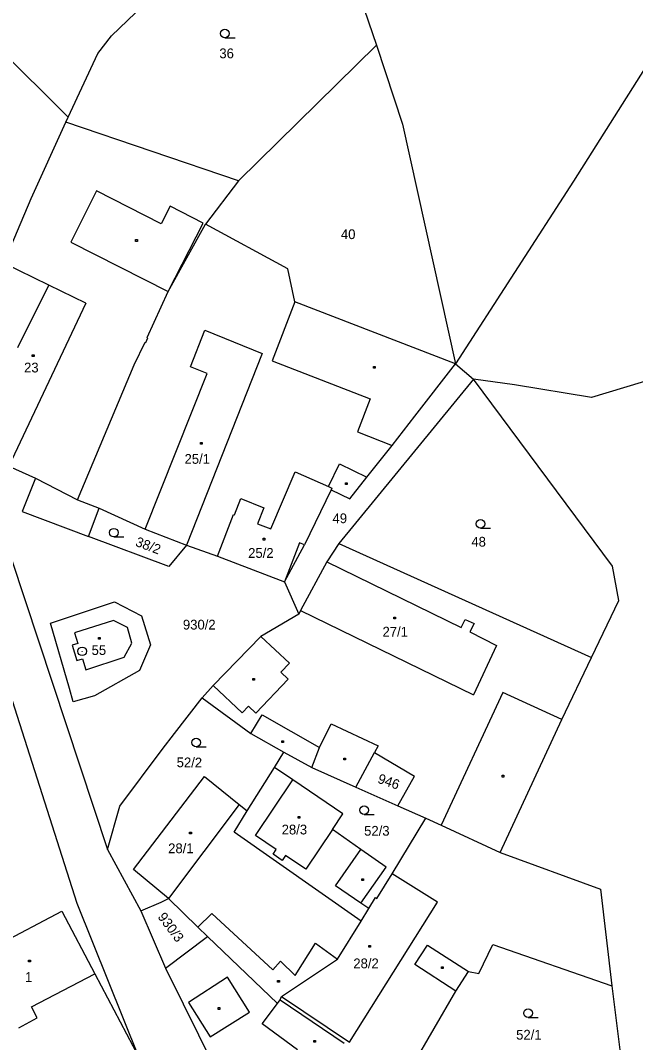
# Model space of a CAD drawing. Extents: x -796130 to -793145, y -1109506 to -1106267.
# Drawn here: x -794498.3 to -794391.3, y -1107830.1 to -1107652.3 of the extents above; entities that cross this region are included whole.
import ezdxf

# ---------------------------------------------------------------- set-up
doc = ezdxf.new("R2010")
doc.units = 0
for name, color, linetype in [('Vrstva 1', 7, 'Continuous'), ('Vrstva 14', 7, 'Continuous'), ('Vrstva 15', 7, 'Continuous'), ('Vrstva 2', 7, 'Continuous'), ('Vrstva 23', 7, 'Continuous'), ('Vrstva 25', 7, 'Continuous'), ('Vrstva 28', 7, 'Continuous')]:
    doc.layers.add(name, color=color, linetype=linetype)

msp = doc.modelspace()

# ---------------------------------------------------------------- linework, layer by layer
at = {"layer": 'Vrstva 1'}
for p, q in [((-794482.48, -1107655.02), (-794453.53, -1107627.17)), ((-794441.8, -1107640.76), (-794436.37, -1107656.6)), ((-794382.04, -1107648.53), (-794402.09, -1107680.28)), ((-794505.95, -1107653.34), (-794489.99, -1107669.12)), ((-794484.84, -1107658.08), (-794482.48, -1107655.02)), ((-794436.37, -1107656.6), (-794460.35, -1107680.23)), ((-794436.37, -1107656.6), (-794431.83, -1107670.33)), ((-794489.99, -1107669.12), (-794484.84, -1107658.08)), ((-794490.38, -1107669.98), (-794489.99, -1107669.12)), ((-794496.41, -1107683.31), (-794490.38, -1107669.98)), ((-794460.35, -1107680.23), (-794490.38, -1107669.98)), ((-794431.83, -1107670.33), (-794422.61, -1107712.07)), ((-794460.35, -1107680.23), (-794466.1, -1107687.77)), ((-794402.09, -1107680.28), (-794422.61, -1107712.07)), ((-794501.21, -1107694.54), (-794496.41, -1107683.31)), ((-794472.62, -1107699.47), (-794466.1, -1107687.77)), ((-794451.75, -1107695.51), (-794466.1, -1107687.77)), ((-794493.34, -1107698.36), (-794501.21, -1107694.54)), ((-794450.55, -1107701.26), (-794451.75, -1107695.51)), ((-794498.75, -1107709.22), (-794493.34, -1107698.36)), ((-794476.26, -1107707.48), (-794472.62, -1107699.47)), ((-794422.61, -1107712.07), (-794450.55, -1107701.26)), ((-794478.52, -1107712.24), (-794476.62, -1107708.28)), ((-794476.62, -1107708.28), (-794476.48, -1107708.35)), ((-794476.48, -1107708.35), (-794476.12, -1107707.54)), ((-794476.12, -1107707.54), (-794476.26, -1107707.48)), ((-794488.39, -1107735.72), (-794478.52, -1107712.24)), ((-794429.7, -1107721.12), (-794422.61, -1107712.07)), ((-794422.61, -1107712.07), (-794419.45, -1107714.72)), ((-794382.35, -1107712.86), (-794398.91, -1107717.92)), ((-794419.45, -1107714.72), (-794442.9, -1107743.28)), ((-794395.26, -1107747.22), (-794419.45, -1107714.72)), ((-794412.32, -1107715.7), (-794419.45, -1107714.72)), ((-794398.91, -1107717.92), (-794412.32, -1107715.7)), ((-794433.65, -1107726.24), (-794429.7, -1107721.12)), ((-794438.02, -1107731.74), (-794433.65, -1107726.24)), ((-794506.09, -1107727.3), (-794483.18, -1107796.53)), ((-794500.34, -1107729.85), (-794495.7, -1107731.95)), ((-794495.7, -1107731.95), (-794498.02, -1107737.75)), ((-794454.75, -1107740.77), (-794450.53, -1107730.83)), ((-794450.53, -1107730.83), (-794444.72, -1107733.38)), ((-794441, -1107735.5), (-794438.02, -1107731.74)), ((-794444.72, -1107733.38), (-794444.11, -1107733.65)), ((-794444.11, -1107733.65), (-794444.26, -1107733.95)), ((-794461.04, -1107738.32), (-794459.97, -1107735.49)), ((-794459.97, -1107735.49), (-794455.96, -1107737.08)), ((-794444.26, -1107733.95), (-794448.85, -1107743.51)), ((-794444.26, -1107733.95), (-794441, -1107735.5)), ((-794488.39, -1107735.72), (-794484.6, -1107737.13)), ((-794486.45, -1107742.05), (-794484.6, -1107737.13)), ((-794484.6, -1107737.13), (-794476.6, -1107740.79)), ((-794455.96, -1107737.08), (-794457.03, -1107739.9)), ((-794498.02, -1107737.75), (-794486.45, -1107742.05)), ((-794464.03, -1107745.51), (-794461.21, -1107738.26)), ((-794461.21, -1107738.26), (-794461.04, -1107738.32)), ((-794476.6, -1107740.79), (-794469.41, -1107743.61)), ((-794457.03, -1107739.9), (-794454.75, -1107740.77)), ((-794472.51, -1107747.3), (-794486.45, -1107742.05)), ((-794469.41, -1107743.61), (-794472.51, -1107747.3)), ((-794469.41, -1107743.61), (-794464.03, -1107745.51)), ((-794452.37, -1107749.98), (-794448.85, -1107743.51)), ((-794442.9, -1107743.28), (-794445, -1107746.46)), ((-794442.9, -1107743.28), (-794398.95, -1107763.14)), ((-794464.03, -1107745.51), (-794452.37, -1107749.98)), ((-794445, -1107746.46), (-794449.56, -1107754.93)), ((-794394.2, -1107753.2), (-794395.26, -1107747.22)), ((-794452.37, -1107749.98), (-794449.87, -1107755.61)), ((-794488.44, -1107805.91), (-794505.52, -1107752.46)), ((-794398.95, -1107763.14), (-794394.2, -1107753.2)), ((-794493.07, -1107757.13), (-794481.91, -1107753.47)), ((-794481.91, -1107753.47), (-794477.23, -1107755.89)), ((-794449.56, -1107754.93), (-794449.87, -1107755.61)), ((-794477.23, -1107755.89), (-794475.7, -1107760.9)), ((-794449.87, -1107755.61), (-794456.45, -1107759.45)), ((-794489.79, -1107768.5), (-794493.07, -1107757.13)), ((-794456.45, -1107759.45), (-794464.79, -1107768.01)), ((-794475.7, -1107760.9), (-794477.6, -1107765.39)), ((-794404.1, -1107773.92), (-794398.95, -1107763.14)), ((-794477.6, -1107765.39), (-794485.43, -1107769.78)), ((-794489.11, -1107770.86), (-794489.79, -1107768.5)), ((-794464.79, -1107768.01), (-794466.67, -1107770.15)), ((-794485.43, -1107769.78), (-794489.11, -1107770.86)), ((-794471.5, -1107776.37), (-794466.67, -1107770.15)), ((-794466.67, -1107770.15), (-794458.22, -1107776.36)), ((-794414.84, -1107797.02), (-794404.1, -1107773.92)), ((-794473.65, -1107779.15), (-794471.5, -1107776.37)), ((-794458.22, -1107776.36), (-794452.45, -1107779.58)), ((-794481.02, -1107788.97), (-794473.65, -1107779.15)), ((-794454.1, -1107782.23), (-794452.45, -1107779.58)), ((-794452.45, -1107779.58), (-794447.59, -1107782.27)), ((-794439.97, -1107785.68), (-794436.72, -1107779.66)), ((-794436.72, -1107779.66), (-794429.75, -1107783.76)), ((-794458.83, -1107789.82), (-794454.1, -1107782.23)), ((-794450.92, -1107784.39), (-794454.1, -1107782.23)), ((-794447.59, -1107782.27), (-794439.97, -1107785.68)), ((-794478.64, -1107800), (-794466.3, -1107783.82)), ((-794466.3, -1107783.82), (-794460.24, -1107788.69)), ((-794442.19, -1107790.32), (-794450.92, -1107784.39)), ((-794432.61, -1107788.93), (-794429.75, -1107783.76)), ((-794439.97, -1107785.68), (-794432.61, -1107788.93)), ((-794483.18, -1107796.53), (-794481.02, -1107788.97)), ((-794460.24, -1107788.69), (-794458.83, -1107789.82)), ((-794432.61, -1107788.93), (-794427.74, -1107791.09)), ((-794461.11, -1107793.49), (-794458.83, -1107789.82)), ((-794444.01, -1107793.03), (-794442.19, -1107790.32)), ((-794433.65, -1107800.74), (-794427.74, -1107791.09)), ((-794427.74, -1107791.09), (-794425.07, -1107792.27)), ((-794425.07, -1107792.27), (-794414.84, -1107797.02)), ((-794439.04, -1107809.01), (-794461.11, -1107793.49)), ((-794439.07, -1107796.51), (-794444.01, -1107793.03)), ((-794483.18, -1107796.53), (-794477.35, -1107807.18)), ((-794434.69, -1107799.61), (-794439.07, -1107796.51)), ((-794414.84, -1107797.02), (-794397.36, -1107803.4)), ((-794439.09, -1107805.87), (-794434.69, -1107799.61)), ((-794472.53, -1107805.03), (-794478.64, -1107800)), ((-794436.29, -1107805.04), (-794433.65, -1107800.74)), ((-794437.68, -1107806.79), (-794436.5, -1107804.89)), ((-794436.5, -1107804.89), (-794436.29, -1107805.04)), ((-794397.36, -1107803.4), (-794395.39, -1107820.21)), ((-794477.65, -1107832.78), (-794488.44, -1107805.91)), ((-794477.35, -1107807.18), (-794473.81, -1107805.66)), ((-794473.81, -1107805.66), (-794472.53, -1107805.03)), ((-794467.46, -1107810.01), (-794472.53, -1107805.03)), ((-794437.68, -1107806.79), (-794439.09, -1107805.87)), ((-794521.11, -1107823.01), (-794491.09, -1107807.24)), ((-794491.09, -1107807.24), (-794485.37, -1107818.12)), ((-794477.35, -1107807.18), (-794473.05, -1107817.18)), ((-794439.04, -1107809.01), (-794437.68, -1107806.79)), ((-794465.73, -1107811.67), (-794467.46, -1107810.01)), ((-794443.11, -1107815.6), (-794439.04, -1107809.01)), ((-794473.05, -1107817.18), (-794465.73, -1107811.67)), ((-794465.73, -1107811.67), (-794453.58, -1107823.33)), ((-794418.56, -1107818.08), (-794416.08, -1107813.05)), ((-794416.08, -1107813.05), (-794395.39, -1107820.21)), ((-794452.88, -1107822.06), (-794443.11, -1107815.6)), ((-794473.05, -1107817.18), (-794470, -1107823.36)), ((-794485.37, -1107818.12), (-794477.65, -1107832.78)), ((-794422.52, -1107821.15), (-794420.33, -1107817.76)), ((-794420.33, -1107817.76), (-794418.56, -1107818.08)), ((-794395.39, -1107820.21), (-794393.06, -1107838.97)), ((-794453.58, -1107823.33), (-794453.1, -1107822.64)), ((-794453.1, -1107822.64), (-794452.88, -1107822.06)), ((-794453.1, -1107822.64), (-794441.95, -1107830.18)), ((-794430.51, -1107834.81), (-794422.52, -1107821.15)), ((-794470, -1107823.36), (-794462.61, -1107838.31))]:
    msp.add_line(p, q, dxfattribs=at)
at = {"layer": 'Vrstva 2'}
for p, q in [((-794485.07, -1107681.94), (-794489.51, -1107690.89)), ((-794473.82, -1107687.69), (-794485.07, -1107681.94)), ((-794472.25, -1107684.61), (-794473.82, -1107687.69)), ((-794466.5, -1107687.56), (-794472.25, -1107684.61)), ((-794472.62, -1107699.47), (-794466.5, -1107687.56)), ((-794489.51, -1107690.89), (-794472.62, -1107699.47)), ((-794486.91, -1107701.49), (-794493.34, -1107698.36)), ((-794486.91, -1107701.49), (-794500.34, -1107729.85)), ((-794450.55, -1107701.26), (-794454.51, -1107711.5)), ((-794468.7, -1107712.55), (-794466.21, -1107706.16)), ((-794466.21, -1107706.16), (-794456.24, -1107710.25)), ((-794456.24, -1107710.25), (-794469.41, -1107743.61)), ((-794465.8, -1107713.72), (-794468.7, -1107712.55)), ((-794454.51, -1107711.5), (-794437.46, -1107718.14)), ((-794476.6, -1107740.79), (-794465.8, -1107713.72)), ((-794437.46, -1107718.14), (-794439.67, -1107723.89)), ((-794439.67, -1107723.89), (-794433.65, -1107726.24)), ((-794444.72, -1107733.38), (-794442.77, -1107729.41)), ((-794442.77, -1107729.41), (-794438.02, -1107731.74)), ((-794495.7, -1107731.95), (-794488.39, -1107735.72)), ((-794449.73, -1107743.19), (-794452.37, -1107749.98)), ((-794448.85, -1107743.51), (-794449.73, -1107743.19)), ((-794445, -1107746.46), (-794421.64, -1107757.91)), ((-794449.56, -1107754.93), (-794419.49, -1107769.6)), ((-794482.11, -1107756.7), (-794488.87, -1107758.84)), ((-794479.66, -1107757.92), (-794482.11, -1107756.7)), ((-794421.64, -1107757.91), (-794420.94, -1107756.53)), ((-794420.94, -1107756.53), (-794419.35, -1107757.19)), ((-794478.91, -1107760.64), (-794479.66, -1107757.92)), ((-794419.35, -1107757.19), (-794420.1, -1107758.68)), ((-794420.1, -1107758.68), (-794415.47, -1107761.02)), ((-794488.87, -1107758.84), (-794488.32, -1107760.67)), ((-794451.47, -1107764.12), (-794456.45, -1107759.45)), ((-794488.32, -1107760.67), (-794489.29, -1107760.96)), ((-794489.29, -1107760.96), (-794488.48, -1107763.65)), ((-794480.23, -1107763.05), (-794478.91, -1107760.64)), ((-794415.47, -1107761.02), (-794419.49, -1107769.6)), ((-794488.48, -1107763.65), (-794487.52, -1107763.36)), ((-794487.52, -1107763.36), (-794486.95, -1107765.27)), ((-794486.95, -1107765.27), (-794480.23, -1107763.05)), ((-794452.98, -1107765.7), (-794451.47, -1107764.12)), ((-794451.73, -1107766.89), (-794452.98, -1107765.7)), ((-794457.34, -1107772.82), (-794451.73, -1107766.89)), ((-794464.79, -1107768.01), (-794459.74, -1107772.77)), ((-794414.36, -1107769.22), (-794425.07, -1107792.27)), ((-794404.1, -1107773.92), (-794414.36, -1107769.22)), ((-794459.74, -1107772.77), (-794458.62, -1107771.6)), ((-794458.62, -1107771.6), (-794457.34, -1107772.82)), ((-794458.22, -1107776.36), (-794456.24, -1107773.11)), ((-794456.24, -1107773.11), (-794446.28, -1107778.79)), ((-794446.28, -1107778.79), (-794444.21, -1107774.65)), ((-794444.21, -1107774.65), (-794436.08, -1107778.47)), ((-794447.59, -1107782.27), (-794446.28, -1107778.79)), ((-794436.08, -1107778.47), (-794436.72, -1107779.66)), ((-794457.42, -1107794.08), (-794450.92, -1107784.39)), ((-794460.24, -1107788.69), (-794472.53, -1107805.03)), ((-794453.78, -1107796.52), (-794457.42, -1107794.08)), ((-794444.01, -1107793.03), (-794448.66, -1107799.95)), ((-794454.35, -1107797.36), (-794453.78, -1107796.52)), ((-794452.78, -1107798.41), (-794454.35, -1107797.36)), ((-794452.21, -1107797.57), (-794452.78, -1107798.41)), ((-794448.66, -1107799.95), (-794452.21, -1107797.57)), ((-794443.51, -1107802.86), (-794439.07, -1107796.51)), ((-794425.74, -1107805.66), (-794433.65, -1107800.74)), ((-794439.09, -1107805.87), (-794443.51, -1107802.86)), ((-794441.06, -1107830.02), (-794425.74, -1107805.66)), ((-794467.46, -1107810.01), (-794465.03, -1107807.66)), ((-794465.03, -1107807.66), (-794454.38, -1107817.43)), ((-794450.51, -1107818.46), (-794446.94, -1107812.82)), ((-794446.94, -1107812.82), (-794443.11, -1107815.6)), ((-794429.69, -1107816.51), (-794427.49, -1107813.15)), ((-794427.49, -1107813.15), (-794420.33, -1107817.76)), ((-794454.38, -1107817.43), (-794453.04, -1107815.97)), ((-794453.04, -1107815.97), (-794450.51, -1107818.46)), ((-794422.52, -1107821.15), (-794429.69, -1107816.51)), ((-794496.4, -1107823.91), (-794485.37, -1107818.12)), ((-794462.3, -1107818.75), (-794469.05, -1107823.15)), ((-794458.47, -1107824.8), (-794462.3, -1107818.75)), ((-794452.88, -1107822.06), (-794441.06, -1107830.02)), ((-794495.4, -1107825.82), (-794496.4, -1107823.91)), ((-794469.05, -1107823.15), (-794465.3, -1107829.12)), ((-794456.22, -1107826.85), (-794453.58, -1107823.33)), ((-794498.59, -1107827.51), (-794495.4, -1107825.82)), ((-794465.3, -1107829.12), (-794458.47, -1107824.8)), ((-794450.08, -1107831.37), (-794456.22, -1107826.85))]:
    msp.add_line(p, q, dxfattribs=at)
at = {"layer": 'Vrstva 23'}
for p, q in [((-794462.72, -1107655.32), (-794460.97, -1107655.32)), ((-794418.26, -1107740.61), (-794416.51, -1107740.61)), ((-794482.07, -1107742.16), (-794480.32, -1107742.16)), ((-794467.74, -1107778.67), (-794465.99, -1107778.67)), ((-794438.5, -1107790.42), (-794436.75, -1107790.42)), ((-794409.98, -1107825.75), (-794408.23, -1107825.75))]:
    msp.add_line(p, q, dxfattribs=at)
for centre in [(-794462.72, -1107654.57), (-794418.26, -1107739.86), (-794482.07, -1107741.41), (-794467.74, -1107777.92), (-794438.5, -1107789.67), (-794409.98, -1107825)]:
    msp.add_circle(centre, 0.75, dxfattribs=at)
at = {"layer": 'Vrstva 25'}
for p, q in [((-794478.26, -1107690.44), (-794477.96, -1107690.44)), ((-794478.26, -1107690.74), (-794478.26, -1107690.44)), ((-794477.96, -1107690.74), (-794478.26, -1107690.74)), ((-794477.96, -1107690.44), (-794477.96, -1107690.74)), ((-794496.24, -1107710.48), (-794495.94, -1107710.48)), ((-794496.24, -1107710.78), (-794496.24, -1107710.48)), ((-794495.94, -1107710.48), (-794495.94, -1107710.78)), ((-794495.94, -1107710.78), (-794496.24, -1107710.78)), ((-794436.87, -1107712.49), (-794436.57, -1107712.49)), ((-794436.87, -1107712.79), (-794436.87, -1107712.49)), ((-794436.57, -1107712.49), (-794436.57, -1107712.79)), ((-794436.57, -1107712.79), (-794436.87, -1107712.79)), ((-794466.96, -1107725.74), (-794466.66, -1107725.74)), ((-794466.96, -1107726.04), (-794466.96, -1107725.74)), ((-794466.66, -1107726.04), (-794466.96, -1107726.04)), ((-794466.66, -1107725.74), (-794466.66, -1107726.04)), ((-794441.76, -1107732.76), (-794441.46, -1107732.76)), ((-794441.76, -1107733.06), (-794441.76, -1107732.76)), ((-794441.46, -1107733.06), (-794441.76, -1107733.06)), ((-794441.46, -1107732.76), (-794441.46, -1107733.06)), ((-794456.08, -1107742.39), (-794455.78, -1107742.39)), ((-794456.08, -1107742.69), (-794456.08, -1107742.39)), ((-794455.78, -1107742.69), (-794456.08, -1107742.69)), ((-794455.78, -1107742.39), (-794455.78, -1107742.69)), ((-794433.34, -1107756.1), (-794433.04, -1107756.1)), ((-794433.34, -1107756.4), (-794433.34, -1107756.1)), ((-794433.04, -1107756.4), (-794433.34, -1107756.4)), ((-794433.04, -1107756.1), (-794433.04, -1107756.4)), ((-794484.72, -1107759.65), (-794484.42, -1107759.65)), ((-794484.72, -1107759.95), (-794484.72, -1107759.65)), ((-794484.42, -1107759.95), (-794484.72, -1107759.95)), ((-794484.42, -1107759.65), (-794484.42, -1107759.95)), ((-794457.87, -1107766.75), (-794457.57, -1107766.75)), ((-794457.87, -1107767.05), (-794457.87, -1107766.75)), ((-794457.57, -1107767.05), (-794457.87, -1107767.05)), ((-794457.57, -1107766.75), (-794457.57, -1107767.05)), ((-794452.82, -1107777.61), (-794452.52, -1107777.61)), ((-794452.82, -1107777.91), (-794452.82, -1107777.61)), ((-794452.52, -1107777.91), (-794452.82, -1107777.91)), ((-794452.52, -1107777.61), (-794452.52, -1107777.91)), ((-794442.02, -1107780.65), (-794441.72, -1107780.65)), ((-794442.02, -1107780.95), (-794442.02, -1107780.65)), ((-794441.72, -1107780.95), (-794442.02, -1107780.95)), ((-794441.72, -1107780.65), (-794441.72, -1107780.95)), ((-794414.51, -1107783.61), (-794414.21, -1107783.61)), ((-794414.51, -1107783.91), (-794414.51, -1107783.61)), ((-794414.21, -1107783.61), (-794414.21, -1107783.91)), ((-794414.21, -1107783.91), (-794414.51, -1107783.91)), ((-794450, -1107790.77), (-794449.7, -1107790.77)), ((-794450, -1107791.07), (-794450, -1107790.77)), ((-794449.7, -1107790.77), (-794449.7, -1107791.07)), ((-794449.7, -1107791.07), (-794450, -1107791.07)), ((-794468.86, -1107793.5), (-794468.56, -1107793.5)), ((-794468.86, -1107793.8), (-794468.86, -1107793.5)), ((-794468.56, -1107793.8), (-794468.86, -1107793.8)), ((-794468.56, -1107793.5), (-794468.56, -1107793.8)), ((-794438.9, -1107801.64), (-794438.6, -1107801.64)), ((-794438.9, -1107801.94), (-794438.9, -1107801.64)), ((-794438.6, -1107801.94), (-794438.9, -1107801.94)), ((-794438.6, -1107801.64), (-794438.6, -1107801.94)), ((-794437.67, -1107813.23), (-794437.37, -1107813.23)), ((-794437.67, -1107813.53), (-794437.67, -1107813.23)), ((-794437.37, -1107813.53), (-794437.67, -1107813.53)), ((-794437.37, -1107813.23), (-794437.37, -1107813.53)), ((-794496.88, -1107815.75), (-794496.58, -1107815.75)), ((-794496.88, -1107816.05), (-794496.88, -1107815.75)), ((-794496.58, -1107816.05), (-794496.88, -1107816.05)), ((-794496.58, -1107815.75), (-794496.58, -1107816.05)), ((-794425.02, -1107816.93), (-794424.72, -1107816.93)), ((-794425.02, -1107817.23), (-794425.02, -1107816.93)), ((-794424.72, -1107817.23), (-794425.02, -1107817.23)), ((-794424.72, -1107816.93), (-794424.72, -1107817.23)), ((-794453.55, -1107819.32), (-794453.25, -1107819.32)), ((-794453.55, -1107819.62), (-794453.55, -1107819.32)), ((-794453.25, -1107819.62), (-794453.55, -1107819.62)), ((-794453.25, -1107819.32), (-794453.25, -1107819.62)), ((-794463.89, -1107824.03), (-794463.59, -1107824.03)), ((-794463.89, -1107824.33), (-794463.89, -1107824.03)), ((-794463.59, -1107824.33), (-794463.89, -1107824.33)), ((-794463.59, -1107824.03), (-794463.59, -1107824.33)), ((-794447.25, -1107829.72), (-794446.95, -1107829.72)), ((-794447.25, -1107830.02), (-794447.25, -1107829.72)), ((-794446.95, -1107829.72), (-794446.95, -1107830.02)), ((-794446.95, -1107830.02), (-794447.25, -1107830.02))]:
    msp.add_line(p, q, dxfattribs=at)
at = {"layer": 'Vrstva 28'}
for radius in [0.75, 0.01]:
    msp.add_circle((-794487.55, -1107762.05), radius, dxfattribs=at)

# ---------------------------------------------------------------- texts
at = {"layer": 'Vrstva 14'}
for s, p in [('36', (-794463.69, -1107658.89)), ('40', (-794442.54, -1107690.35)), ('49', (-794444, -1107739.76)), ('48', (-794419.84, -1107743.84)), ('930/2', (-794470.03, -1107758.26)), ('52/3', (-794438.5, -1107794.12)), ('52/1', (-794412.05, -1107829.59))]:
    msp.add_text(s, height=1.7, dxfattribs=at).set_placement(p)
for s, rotation, p in [('38/2', 339.46938, (-794478.43, -1107743.67)), ('52/2', 359.28108, (-794471.13, -1107782.2)), ('946', 340.95996, (-794436.28, -1107784.89)), ('930/3', 306.84411, (-794474.51, -1107808.26))]:
    msp.add_text(s, height=1.7, rotation=rotation, dxfattribs=at).set_placement(p)
at = {"layer": 'Vrstva 15'}
for s, p in [('23', (-794497.67, -1107713.54)), ('25/1', (-794469.75, -1107729.43)), ('25/2', (-794458.68, -1107745.79)), ('27/1', (-794435.3, -1107759.49)), ('55', (-794485.92, -1107762.68)), ('28/3', (-794452.85, -1107793.9)), ('28/1', (-794472.6, -1107797.16)), ('28/2', (-794440.38, -1107817.18)), ('1', (-794497.51, -1107819.55))]:
    msp.add_text(s, height=1.7, dxfattribs=at).set_placement(p)

doc.saveas('drawing.dxf')
